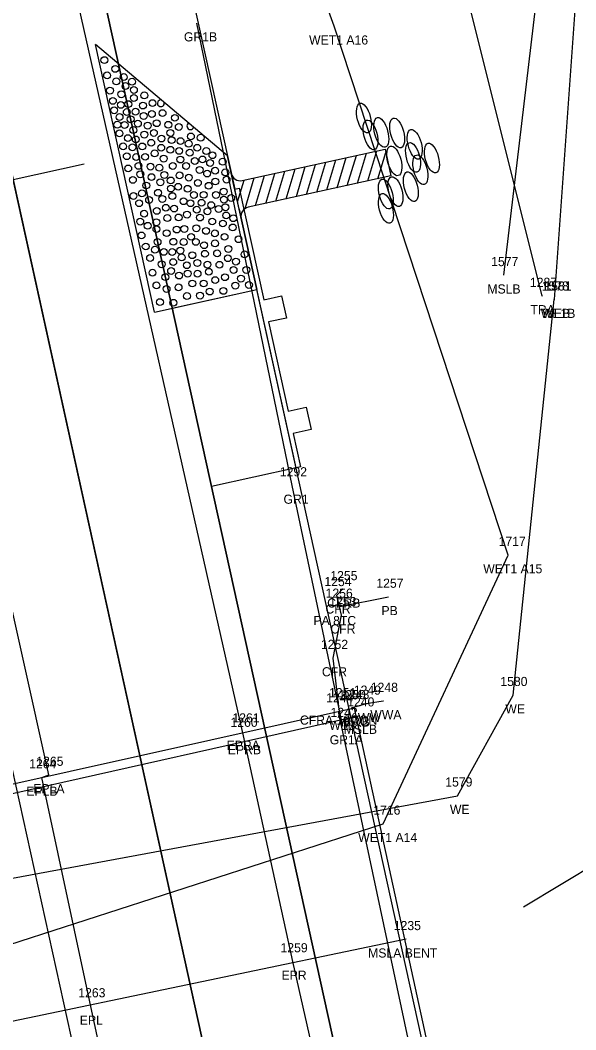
# Model space of a CAD drawing. Extents: x 2521558 to 2524785, y 882711 to 887632.
# Drawn here: x 2523768.4 to 2523829.3, y 885126.7 to 885237.2 of the extents above; entities that cross this region are included whole.
import ezdxf

# ---------------------------------------------------------------- set-up
doc = ezdxf.new("R2010")
doc.units = 0
for name, color, linetype in [('RD_EV_JurisArea', 7, 'Continuous'), ('RD_EX_BldgApp', 7, 'Continuous'), ('RD_EX_BldgApp_txCode', 7, 'Continuous'), ('RD_EX_Bridge', 7, 'Continuous'), ('RD_EX_Bridge_txCode', 7, 'Continuous'), ('RD_EX_Conc', 7, 'Continuous'), ('RD_EX_Conc_txCode', 7, 'Continuous'), ('RD_EX_DR_Pipe', 7, 'Continuous'), ('RD_EX_DR_Pipe_txCode', 7, 'Continuous'), ('RD_EX_GuardRail', 7, 'Continuous'), ('RD_EX_GuardRail_txCode', 7, 'Continuous'), ('RD_EX_H2O', 7, 'Continuous'), ('RD_EX_H2O_txCode', 7, 'Continuous'), ('RD_EX_H2O_WetLd_txCode', 7, 'Continuous'), ('RD_EX_Misc', 7, 'Continuous'), ('RD_EX_Misc_txCode', 7, 'Continuous'), ('RD_EX_Road', 7, 'Continuous'), ('RD_EX_Road_txCode', 7, 'Continuous'), ('RD_EX_VEG', 7, 'Continuous'), ('RD_EX_VEG_txCode', 7, 'Continuous'), ('RD_HC_Cl', 7, 'Continuous'), ('RD_HC_Data_Tic', 7, 'Continuous'), ('RD_PD_Bridge', 7, 'Continuous'), ('RD_PD_Final_TrvlWay', 7, 'Continuous'), ('RD_PD_GR', 7, 'Continuous'), ('RD_PD_PaveShd', 7, 'Continuous'), ('RD_PD_SuperShp1', 7, 'Continuous'), ('RD_SMD_Locator', 7, 'Continuous')]:
    doc.layers.add(name, color=color, linetype=linetype)

# ---------------------------------------------------------------- blocks, each defined once
blk = doc.blocks.new('TBC1')
at = {"layer": 'RD_PD_GR'}
blk.add_lwpolyline([(12.5, 2.5), (15, 2.5), (15, 0.49), (25, 0.49), (25, 2.5), (27.5, 2.5), (27.5, 0.49), (31.25, 0.49), (31.25, 0), (0, 0), (0, 0.49), (12.5, 0.49)], close=True, dxfattribs=at)

msp = doc.modelspace()

# ---------------------------------------------------------------- linework, layer by layer
at = {"layer": 'RD_EV_JurisArea'}
msp.add_lwpolyline([(2523761.17, 885134.03), (2523808.21, 885149.21), (2523821.91, 885178.64), (2523802.85, 885236.55), (2523777.81, 885305.56), (2523748.2, 885444.32), (2523730.68, 885516.88), (2523708.64, 885617.3), (2523698.71, 885662.02), (2523727.83, 885665.82), (2523757.3, 885671.75)], dxfattribs=at)
at = {"layer": 'RD_EX_BldgApp'}
msp.add_lwpolyline([(2523819.44, 885087.44), (2523811.32, 885123.96), (2523803.31, 885161.5)], dxfattribs=at)
at = {"layer": 'RD_EX_Bridge'}
for points in [[(2523774.91, 885077.6), (2523821.2, 885087.83), (2523805.06, 885161.89), (2523758.15, 885151.44), (2523774.91, 885077.6)], [(2523808.19, 885162.66), (2523806.34, 885162.35), (2523804.71, 885161.86)]]:
    msp.add_lwpolyline(points, dxfattribs=at)
at = {"layer": 'RD_EX_Conc'}
msp.add_lwpolyline([(2523803.34, 885162.07), (2523802.73, 885167.36), (2523803.65, 885172.05), (2523803.12, 885174.24), (2523803.77, 885174.89)], dxfattribs=at)
at = {"layer": 'RD_EX_DR_Pipe'}
msp.add_line((2523803.27, 885172.97), (2523808.8, 885174.06), dxfattribs=at)
at = {"layer": 'RD_EX_GuardRail'}
msp.add_lwpolyline([(2523803.79, 885159.91), (2523798.24, 885186.26), (2523787.8, 885236.89)], dxfattribs=at)
at = {"layer": 'RD_EX_H2O'}
for points in [[(2524064.86, 885165.15), (2524036.37, 885213.78), (2524057.22, 885252.72), (2524031.95, 885291.63), (2523983.25, 885326.3), (2523940.61, 885311.83), (2523904.84, 885305.01), (2523874.98, 885272.1), (2523850.32, 885280.24), (2523830.66, 885258.8), (2523826.93, 885206.61)], [(2523738.91, 885147.5), (2523743.69, 885138.84), (2523816.36, 885152.29), (2523822.43, 885163.3), (2523826.93, 885206.61)]]:
    msp.add_lwpolyline(points, dxfattribs=at)
at = {"layer": 'RD_EX_Misc'}
for p, q in [((2523758.45, 885150.47), (2523805.66, 885161.06)), ((2523810.71, 885136.57), (2523763.83, 885126.8))]:
    msp.add_line(p, q, dxfattribs=at)
msp.add_lwpolyline([(2524066.31, 885165.35), (2524037.3, 885214.15), (2524057.95, 885253.07), (2524039.52, 885283.17), (2524032.92, 885292.57), (2523983.53, 885327.98), (2523940.24, 885313.27), (2523904.13, 885306.25), (2523874.86, 885272.67), (2523849.96, 885282.51), (2523827.65, 885261.93), (2523821.38, 885209.28)], dxfattribs=at)
at = {"layer": 'RD_EX_Road'}
for p, q in [((2523792.78, 885159.31), (2523771.24, 885254.79)), ((2523771.58, 885154.56), (2523750.32, 885250.18)), ((2523792.89, 885158.83), (2523792.78, 885159.31)), ((2523798.3, 885134.14), (2523792.89, 885158.83)), ((2523770.8, 885154.29), (2523771.58, 885154.56)), ((2523776.18, 885129.21), (2523770.8, 885154.29)), ((2523803.79, 885109.94), (2523798.3, 885134.14)), ((2523781.52, 885104.77), (2523776.18, 885129.21))]:
    msp.add_line(p, q, dxfattribs=at)
at = {"layer": 'RD_EX_VEG'}
msp.add_lwpolyline([(2523825.62, 885207.01), (2523811.87, 885262.11), (2523733.02, 885654.22), (2523687.11, 885876.24)], dxfattribs=at)
at = {"layer": 'RD_HC_Cl'}
for p, q in [((2523641.17, 885794.2), (2524197.76, 883266.56)), ((2523823.59, 885140.12), (2523837.18, 885148.32))]:
    msp.add_line(p, q, dxfattribs=at)
at = {"layer": 'RD_HC_Data_Tic'}
msp.add_line((2523767.66, 885219.76), (2523775.47, 885221.48), dxfattribs=at)
at = {"layer": 'RD_PD_Bridge'}
msp.add_line((2523785.09, 885205.68), (2523794.37, 885207.73), dxfattribs=at)
for points in [[(2523830.93, 885041.7), (2523794.37, 885207.73)], [(2523798.67, 885188.19), (2523789.4, 885186.15)]]:
    msp.add_lwpolyline(points, dxfattribs=at)
at = {"layer": 'RD_PD_Final_TrvlWay'}
for p, q in [((2523724.34, 885481.57), (2524039.39, 884050.85)), ((2523697, 885475.55), (2524012.05, 884044.83))]:
    msp.add_line(p, q, dxfattribs=at)
at = {"layer": 'RD_PD_GR'}
msp.add_line((2523722.6, 885533.67), (2523791.95, 885218.71), dxfattribs=at)
at = {"layer": 'RD_PD_PaveShd'}
for p, q in [((2523783.14, 885205.25), (2523776.69, 885234.55)), ((2523791.15, 885222.37), (2523776.69, 885234.55)), ((2523792.77, 885219.66), (2523808.42, 885223.1)), ((2523806.52, 885219.61), (2523807.5, 885222.9)), ((2523806.52, 885219.61), (2523807.5, 885222.9)), ((2523807.63, 885219.85), (2523808.5, 885222.74)), ((2523807.63, 885219.85), (2523808.5, 885222.74)), ((2523808.42, 885223.1), (2523809.06, 885220.17)), ((2523808.42, 885223.1), (2523809.06, 885220.17)), ((2523791.79, 885219.44), (2523791.15, 885222.37)), ((2523800.93, 885218.38), (2523801.91, 885221.67)), ((2523800.93, 885218.38), (2523801.91, 885221.67)), ((2523802.05, 885218.63), (2523803.03, 885221.91)), ((2523802.05, 885218.63), (2523803.03, 885221.91)), ((2523803.17, 885218.87), (2523804.15, 885222.16)), ((2523803.17, 885218.87), (2523804.15, 885222.16)), ((2523804.28, 885219.12), (2523805.27, 885222.4)), ((2523804.28, 885219.12), (2523805.27, 885222.4)), ((2523805.4, 885219.36), (2523806.38, 885222.65)), ((2523805.4, 885219.36), (2523806.38, 885222.65)), ((2523796.46, 885217.4), (2523797.45, 885220.69)), ((2523796.46, 885217.4), (2523797.45, 885220.69)), ((2523797.58, 885217.64), (2523798.56, 885220.93)), ((2523797.58, 885217.64), (2523798.56, 885220.93)), ((2523798.7, 885217.89), (2523799.68, 885221.18)), ((2523798.7, 885217.89), (2523799.68, 885221.18)), ((2523799.81, 885218.14), (2523800.8, 885221.42)), ((2523799.81, 885218.14), (2523800.8, 885221.42)), ((2523792.44, 885216.52), (2523791.79, 885219.44)), ((2523792.26, 885217.31), (2523792.98, 885219.71)), ((2523793.09, 885216.6), (2523794.09, 885219.95)), ((2523809.06, 885220.17), (2523793.41, 885216.73)), ((2523794.23, 885216.91), (2523795.21, 885220.2)), ((2523794.23, 885216.91), (2523795.21, 885220.2)), ((2523795.34, 885217.15), (2523796.33, 885220.44)), ((2523795.34, 885217.15), (2523796.33, 885220.44)), ((2523792.22, 885217.49), (2523792.22, 885217.49)), ((2523792.44, 885216.52), (2523794.37, 885207.73)), ((2523794.37, 885207.73), (2523792.44, 885216.52)), ((2523783.14, 885205.25), (2523794.37, 885207.73))]:
    msp.add_line(p, q, dxfattribs=at)
for centre in [(2523777.67, 885232.84), (2523777.67, 885232.84), (2523777.97, 885231.17), (2523777.97, 885231.17), (2523778.86, 885231.88), (2523778.86, 885231.88), (2523778.98, 885230.51), (2523778.98, 885230.51), (2523779.79, 885230.99), (2523779.79, 885230.99), (2523780.7, 885230.48), (2523778.28, 885229.5), (2523778.28, 885229.5), (2523779.52, 885229.1), (2523779.52, 885229.1), (2523779.98, 885230), (2523779.98, 885230), (2523780.9, 885229.57), (2523782.04, 885228.98), (2523782.04, 885228.98), (2523778.6, 885228.38), (2523778.6, 885228.38), (2523779.47, 885227.94), (2523779.47, 885227.94), (2523780.29, 885228.02), (2523780.29, 885228.02), (2523780.9, 885228.7), (2523780.9, 885228.7), (2523781.89, 885227.87), (2523781.89, 885227.87), (2523782.94, 885228.13), (2523782.94, 885228.13), (2523778.74, 885227.35), (2523778.74, 885227.35), (2523780.12, 885227.15), (2523780.12, 885227.15), (2523781.08, 885227.19), (2523781.08, 885227.19), (2523782.87, 885226.95), (2523782.87, 885226.95), (2523784.04, 885227.04), (2523784.04, 885227.04), (2523779.08, 885225.77), (2523779.08, 885225.77), (2523779.33, 885226.61), (2523779.33, 885226.61), (2523779.88, 885225.74), (2523779.88, 885225.74), (2523780.54, 885226.37), (2523780.54, 885226.37), (2523781.34, 885225.89), (2523781.34, 885225.89), (2523781.98, 885226.73), (2523781.98, 885226.73), (2523782.41, 885225.67), (2523782.41, 885225.67), (2523783.4, 885225.93), (2523783.4, 885225.93), (2523784.67, 885225.76), (2523784.67, 885225.76), (2523785.39, 885226.52), (2523779.32, 885224.82), (2523779.32, 885224.82), (2523780.83, 885225.18), (2523780.83, 885225.18), (2523782.05, 885224.68), (2523782.05, 885224.68), (2523783.09, 885224.87), (2523783.09, 885224.87), (2523784.9, 885224.87), (2523784.9, 885224.87), (2523785.82, 885225.52), (2523785.82, 885225.52), (2523780.24, 885224.3), (2523780.24, 885224.3), (2523781.11, 885224.15), (2523781.11, 885224.15), (2523782.8, 885223.79), (2523782.8, 885223.79), (2523783.92, 885224.25), (2523783.92, 885224.25), (2523785.03, 885224.08), (2523785.03, 885224.08), (2523786.01, 885223.97), (2523786.01, 885223.97), (2523786.9, 885223.69), (2523786.9, 885223.69), (2523787.14, 885224.48), (2523787.14, 885224.48), (2523788.22, 885224.34), (2523779.72, 885223.4), (2523779.72, 885223.4), (2523780.12, 885222.32), (2523780.12, 885222.32), (2523780.74, 885223.3), (2523780.74, 885223.3), (2523781.82, 885223.39), (2523781.82, 885223.39), (2523783.17, 885222.63), (2523783.17, 885222.63), (2523783.89, 885223.24), (2523783.89, 885223.24), (2523784.9, 885223.02), (2523784.9, 885223.02), (2523785.86, 885222.9), (2523785.86, 885222.9), (2523787.02, 885222.7), (2523787.02, 885222.7), (2523787.84, 885223.24), (2523787.84, 885223.24), (2523788.83, 885222.88), (2523788.83, 885222.88), (2523789.51, 885222.43), (2523781.15, 885222.23), (2523781.15, 885222.23), (2523781.4, 885221.26), (2523781.4, 885221.26), (2523782.13, 885222.25), (2523782.13, 885222.25), (2523784.16, 885222.05), (2523784.16, 885222.05), (2523785.16, 885221.25), (2523785.16, 885221.25), (2523785.99, 885221.95), (2523785.99, 885221.95), (2523786.62, 885221.25), (2523786.62, 885221.25), (2523787.57, 885221.79), (2523787.57, 885221.79), (2523788.41, 885221.96), (2523788.41, 885221.96), (2523789.25, 885221.58), (2523789.25, 885221.58), (2523789.25, 885221.58), (2523790.63, 885221.72), (2523790.63, 885221.72), (2523780.28, 885220.98), (2523780.28, 885220.98), (2523781.6, 885220.34), (2523781.6, 885220.34), (2523782.72, 885221.18), (2523782.72, 885221.18), (2523783.69, 885221.06), (2523783.69, 885221.06), (2523784.24, 885220.27), (2523784.24, 885220.27), (2523785.9, 885220.22), (2523785.9, 885220.22), (2523788.1, 885220.81), (2523788.1, 885220.81), (2523788.92, 885220.42), (2523788.92, 885220.42), (2523789.8, 885220.73), (2523789.8, 885220.73), (2523790.91, 885220.55), (2523790.91, 885220.55), (2523780.79, 885219.73), (2523780.79, 885219.73), (2523782.26, 885219.11), (2523782.26, 885219.11), (2523782.83, 885220.03), (2523782.83, 885220.03), (2523783.79, 885219.46), (2523783.79, 885219.46), (2523784.93, 885219.66), (2523784.93, 885219.66), (2523786.92, 885219.97), (2523786.92, 885219.97), (2523787.91, 885219.4), (2523787.91, 885219.4), (2523789.1, 885219.08), (2523789.1, 885219.08), (2523789.82, 885219.55), (2523789.82, 885219.55), (2523791.05, 885219.75), (2523791.05, 885219.75), (2523780.85, 885217.97), (2523780.85, 885217.97), (2523781.78, 885218.25), (2523781.78, 885218.25), (2523783.55, 885218.31), (2523783.55, 885218.31), (2523784.95, 885218.78), (2523784.95, 885218.78), (2523785.12, 885217.95), (2523785.12, 885217.95), (2523785.75, 885218.97), (2523785.75, 885218.97), (2523786.79, 885218.75), (2523786.79, 885218.75), (2523787.47, 885218.08), (2523787.47, 885218.08), (2523788.55, 885218.09), (2523788.55, 885218.09), (2523789.89, 885218.08), (2523789.89, 885218.08), (2523790.73, 885218.44), (2523790.73, 885218.44), (2523781.47, 885217.17), (2523781.47, 885217.17), (2523782.57, 885217.53), (2523782.57, 885217.53), (2523784.01, 885217.64), (2523784.01, 885217.64), (2523786.34, 885217.39), (2523786.34, 885217.39), (2523787.1, 885217.17), (2523787.1, 885217.17), (2523788.31, 885217.22), (2523788.31, 885217.22), (2523789.37, 885216.96), (2523789.37, 885216.96), (2523790.76, 885217.56), (2523790.76, 885217.56), (2523791.56, 885217.75), (2523791.56, 885217.75), (2523782.02, 885216.02), (2523782.02, 885216.02), (2523783.41, 885216.33), (2523783.41, 885216.33), (2523784.4, 885216.67), (2523784.4, 885216.67), (2523785.31, 885216.59), (2523785.31, 885216.59), (2523786.72, 885215.92), (2523786.72, 885215.92), (2523787.79, 885216.46), (2523787.79, 885216.46), (2523788.96, 885216.29), (2523788.96, 885216.29), (2523790.18, 885216.54), (2523790.18, 885216.54), (2523790.92, 885216.73), (2523790.92, 885216.73), (2523791.01, 885215.83), (2523781.59, 885215.16), (2523782.41, 885214.7), (2523782.41, 885214.7), (2523783.35, 885215.08), (2523783.35, 885215.08), (2523784.57, 885215.55), (2523784.57, 885215.55), (2523785.8, 885215.61), (2523785.8, 885215.61), (2523788.14, 885215.6), (2523788.14, 885215.6), (2523789.48, 885215.17), (2523789.48, 885215.17), (2523790.65, 885214.95), (2523790.65, 885214.95), (2523791.79, 885215.53), (2523791.79, 885215.53), (2523781.74, 885213.64), (2523781.74, 885213.64), (2523783.37, 885214.33), (2523783.37, 885214.33), (2523784.5, 885213.89), (2523784.5, 885213.89), (2523785.59, 885214.29), (2523785.59, 885214.29), (2523786.42, 885214.35), (2523786.42, 885214.35), (2523787.17, 885213.49), (2523787.17, 885213.49), (2523787.75, 885214.43), (2523787.75, 885214.43), (2523788.8, 885214.14), (2523788.8, 885214.14), (2523789.77, 885213.87), (2523789.77, 885213.87), (2523790.83, 885213.49), (2523790.83, 885213.49), (2523791.73, 885214.52), (2523791.73, 885214.52), (2523782.2, 885212.43), (2523782.2, 885212.43), (2523783.49, 885212.93), (2523783.49, 885212.93), (2523785.23, 885212.95), (2523785.23, 885212.95), (2523786.35, 885212.92), (2523786.35, 885212.92), (2523787.69, 885212.94), (2523787.69, 885212.94), (2523788.59, 885212.57), (2523788.59, 885212.57), (2523789.79, 885212.77), (2523789.79, 885212.77), (2523792.36, 885213.23), (2523792.36, 885213.23), (2523783.21, 885212.08), (2523783.21, 885212.08), (2523784.18, 885211.84), (2523784.18, 885211.84), (2523785.1, 885211.82), (2523785.1, 885211.82), (2523785.98, 885211.98), (2523785.98, 885211.98), (2523787.3, 885211.48), (2523787.3, 885211.48), (2523788.68, 885211.63), (2523788.68, 885211.63), (2523790.02, 885211.68), (2523790.02, 885211.68), (2523791.25, 885212.16), (2523791.25, 885212.16), (2523793.02, 885211.57), (2523793.02, 885211.57), (2523782.68, 885211.17), (2523782.68, 885211.17), (2523783.94, 885210.48), (2523783.94, 885210.48), (2523785.21, 885210.72), (2523785.21, 885210.72), (2523786.14, 885211.24), (2523786.7, 885210.38), (2523786.7, 885210.38), (2523787.85, 885210.63), (2523787.85, 885210.63), (2523788.96, 885210.45), (2523788.96, 885210.45), (2523790.27, 885210.43), (2523790.27, 885210.43), (2523791.19, 885211.15), (2523791.19, 885211.15), (2523792.08, 885210.78), (2523792.08, 885210.78), (2523782.94, 885209.56), (2523782.94, 885209.56), (2523784.35, 885209.08), (2523784.35, 885209.08), (2523784.98, 885209.75), (2523784.98, 885209.75), (2523785.85, 885209.25), (2523785.85, 885209.25), (2523786.79, 885209.46), (2523786.79, 885209.46), (2523787.87, 885209.45), (2523787.87, 885209.45), (2523789.11, 885209.66), (2523789.11, 885209.66), (2523790.88, 885209.07), (2523790.88, 885209.07), (2523791.82, 885209.86), (2523791.82, 885209.86), (2523793.21, 885209.86), (2523793.21, 885209.86), (2523783.37, 885208.17), (2523783.37, 885208.17), (2523787.3, 885208.38), (2523787.3, 885208.38), (2523788.54, 885208.38), (2523788.54, 885208.38), (2523789.81, 885208.75), (2523789.81, 885208.75), (2523792.01, 885208.15), (2523792.01, 885208.15), (2523792.01, 885208.15), (2523792.63, 885208.91), (2523793.5, 885208.22), (2523793.5, 885208.22), (2523784.48, 885207.78), (2523784.48, 885207.78), (2523785.79, 885207.95), (2523785.79, 885207.95), (2523786.71, 885207.01), (2523786.71, 885207.01), (2523788.15, 885207.05), (2523788.15, 885207.05), (2523789.21, 885207.5), (2523789.21, 885207.5), (2523790.7, 885207.57), (2523790.7, 885207.57), (2523783.76, 885206.34), (2523783.76, 885206.34), (2523785.23, 885206.27), (2523785.23, 885206.27)]:
    msp.add_circle(centre, 0.375, dxfattribs=at)
for centre, radius, start, end in [((2523783.86, 885228.12), 0.375, 86.7522, 13.0372), ((2523787.09, 885225.61), 0.375, 117.9394, 341.85), ((2523792.55, 885220.64), 1, 192.4185, 282.3889), ((2523793.63, 885215.75), 1, 102.3889, 192.4185)]:
    msp.add_arc(centre, radius, start, end, dxfattribs=at)
for centre in [(2523806.1, 885226.5), (2523806.82, 885224.65), (2523808, 885224.92), (2523808, 885224.92), (2523809.74, 885224.87), (2523809.74, 885224.87), (2523811.66, 885223.62), (2523811.66, 885223.62), (2523811.48, 885222.18), (2523811.48, 885222.18), (2523813.55, 885222.12), (2523813.55, 885222.12), (2523809.43, 885221.81), (2523809.43, 885221.81), (2523812.28, 885220.83), (2523812.28, 885220.83), (2523811.24, 885218.97), (2523811.24, 885218.97), (2523808.5, 885218.17), (2523808.5, 885218.17), (2523809.55, 885218.44), (2523809.55, 885218.44), (2523808.51, 885216.6), (2523808.51, 885216.6)]:
    msp.add_ellipse(centre, major_axis=(-0.43, 1.62), ratio=0.429445, dxfattribs=at)
at = {"layer": 'RD_PD_SuperShp1'}
for p, q in [((2524039.39, 884050.85), (2523724.34, 885481.57)), ((2524025.72, 884047.84), (2523710.67, 885478.56)), ((2523710.67, 885478.56), (2524025.72, 884047.84)), ((2523697, 885475.55), (2524012.05, 884044.83))]:
    msp.add_line(p, q, dxfattribs=at)
at = {"layer": 'RD_SMD_Locator'}
for centre in [(2523787.8, 885236.89), (2523802.85, 885236.55), (2523821.38, 885209.28), (2523825.62, 885207.01), (2523826.93, 885206.61), (2523826.93, 885206.61), (2523798.24, 885186.26), (2523821.91, 885178.64), (2523803.12, 885174.24), (2523803.77, 885174.89), (2523808.8, 885174.06), (2523803.27, 885172.97), (2523803.65, 885172.05), (2523802.73, 885167.36), (2523822.43, 885163.3), (2523803.34, 885162.07), (2523805.06, 885161.89), (2523806.34, 885162.35), (2523808.19, 885162.66), (2523803.31, 885161.5), (2523804.71, 885161.86), (2523805.66, 885161.06), (2523803.79, 885159.91), (2523792.78, 885159.31), (2523792.89, 885158.83), (2523770.8, 885154.29), (2523771.58, 885154.56), (2523816.36, 885152.29), (2523808.21, 885149.21), (2523810.71, 885136.57), (2523798.3, 885134.14), (2523776.18, 885129.21)]:
    msp.add_circle(centre, 0.001, dxfattribs=at)

# ---------------------------------------------------------------- block references
at = {"layer": 'RD_PD_Bridge', "rotation": -77.58151740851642}
msp.add_blockref('TBC1', (2523791.95, 885218.71), dxfattribs=at)

# ---------------------------------------------------------------- texts
at = {"layer": 'RD_EX_BldgApp_txCode'}
for s, p in [('1244', (2523801.96, 885162.5)), ('W1B', (2523802.3, 885159.5))]:
    msp.add_text(s, height=1, dxfattribs=at).set_placement(p)
at = {"layer": 'RD_EX_Bridge_txCode'}
for s, p in [('1249', (2523804.99, 885163.35)), ('1248', (2523806.85, 885163.66)), ('1250', (2523803.32, 885162.86)), ('1243', (2523803.72, 885162.89)), ('WWB', (2523803.33, 885159.86)), ('BRC', (2523803.81, 885159.89)), ('WW', (2523805.43, 885160.35)), ('WWA', (2523806.8, 885160.66))]:
    msp.add_text(s, height=1, dxfattribs=at).set_placement(p)
at = {"layer": 'RD_EX_Conc_txCode'}
for s, p in [('1255', (2523802.42, 885175.89)), ('1254', (2523801.77, 885175.24)), ('1253', (2523802.3, 885173.05)), ('CFR', (2523801.89, 885172.24)), ('CFRB', (2523802.07, 885172.89)), ('CFR', (2523802.42, 885170.05)), ('1252', (2523801.39, 885168.36)), ('CFR', (2523801.5, 885165.36)), ('1251', (2523802.28, 885163.07)), ('CFRA 18CON', (2523799.09, 885160.07))]:
    msp.add_text(s, height=1, dxfattribs=at).set_placement(p)
at = {"layer": 'RD_EX_DR_Pipe_txCode'}
for s, p in [('1257', (2523807.46, 885175.06)), ('1256', (2523801.9, 885173.97)), ('PB', (2523808.02, 885172.06)), ('PA 8TC', (2523800.57, 885170.97))]:
    msp.add_text(s, height=1, dxfattribs=at).set_placement(p)
at = {"layer": 'RD_EX_GuardRail_txCode'}
for s, p in [('GR1B', (2523786.38, 885234.89)), ('1292', (2523796.89, 885187.26)), ('GR1', (2523797.29, 885184.26)), ('1242', (2523802.44, 885160.91)), ('GR1A', (2523802.35, 885157.91))]:
    msp.add_text(s, height=1, dxfattribs=at).set_placement(p)
at = {"layer": 'RD_EX_H2O_txCode'}
for s, p in [('1578', (2523825.58, 885207.61)), ('1581', (2523825.87, 885207.61)), ('WE1B', (2523825.47, 885204.61)), ('WEB', (2523825.64, 885204.61)), ('1580', (2523821.04, 885164.3)), ('WE', (2523821.59, 885161.3)), ('1579', (2523815.01, 885153.29)), ('WE', (2523815.52, 885150.29))]:
    msp.add_text(s, height=1, dxfattribs=at).set_placement(p)
at = {"layer": 'RD_EX_H2O_WetLd_txCode'}
for s, p in [('WET1 A16', (2523800.09, 885234.55)), ('1717', (2523820.85, 885179.64)), ('WET1 A15', (2523819.17, 885176.64)), ('1716', (2523807.12, 885150.21)), ('WET1 A14', (2523805.47, 885147.21))]:
    msp.add_text(s, height=1, dxfattribs=at).set_placement(p)
at = {"layer": 'RD_EX_Misc_txCode'}
for s, p in [('1577', (2523820.04, 885210.28)), ('MSLB', (2523819.62, 885207.28)), ('1240', (2523804.27, 885162.06)), ('MSLB', (2523803.89, 885159.06)), ('1235', (2523809.37, 885137.57)), ('MSLA BENT', (2523806.56, 885134.57))]:
    msp.add_text(s, height=1, dxfattribs=at).set_placement(p)
at = {"layer": 'RD_EX_Road_txCode'}
for s, p in [('1260', (2523791.48, 885159.83)), ('1261', (2523791.69, 885160.31)), ('EPRA', (2523791.06, 885157.31)), ('EPRB', (2523791.19, 885156.83)), ('1265', (2523770.21, 885155.56)), ('1264', (2523769.43, 885155.29)), ('EPLB', (2523769.12, 885152.29)), ('EPLA', (2523769.88, 885152.56)), ('1259', (2523796.96, 885135.14)), ('EPR', (2523797.07, 885132.14)), ('1263', (2523774.81, 885130.21)), ('EPL', (2523774.97, 885127.21))]:
    msp.add_text(s, height=1, dxfattribs=at).set_placement(p)
at = {"layer": 'RD_EX_VEG_txCode'}
for s, p in [('1287', (2523824.28, 885208.01)), ('TRA', (2523824.34, 885205.01))]:
    msp.add_text(s, height=1, dxfattribs=at).set_placement(p)

doc.saveas('drawing.dxf')
